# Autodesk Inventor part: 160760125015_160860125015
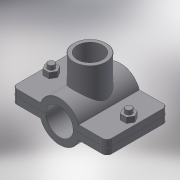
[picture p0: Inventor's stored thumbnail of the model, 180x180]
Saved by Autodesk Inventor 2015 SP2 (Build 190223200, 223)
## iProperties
Created: 2017-05
Part Number: 160760125015_160860125015
Material: Generic
Description: PLASSON SADDLE 125-1.1/2"
Document SubType Name: Modeling
Designer: KIM
Density: 1 g/cm^3
Appearance: Default
Author: KIM
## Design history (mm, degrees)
derived "16076.ipt"
feature "Solid1::16076.ipt"
feature "Solid2::16076.ipt"
tag "TaggingFeature1"
body "Solid1"
other parameters: "d0" = 137.5, "d1" = 184, "d2" = 62.5, "d3" = 125, "d4" = 124, "d5" = 0, "d6" = 9.2, "d7" = 184, "d8" = 0.1, "d10" = 0, "d11" = 1.25, "d14" = 58.2985, "d20" = 1.25, "d23" = 1.25, "d36" = 13, "d37" = 10.4, "d38" = 70.5, "d39" = 0, "d40" = 3, "d41" = 5, "d42" = 0, "d43" = 8, "d44" = 3, "d45" = 0, "d46" = 1.25, "d51" = 99, "d52" = 44.845, "d53" = 25, "d54" = 0, "d57" = 0, "d58" = 135, "d60" = 0, "d62" = 13, "d63" = 10.4, "d66" = 103.2, "d_" = 125, "G_" = 44.845, "A_" = 99, "L_" = 184, "L_1" = 124, "l_2" = 25
